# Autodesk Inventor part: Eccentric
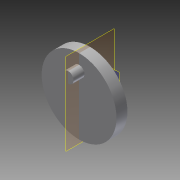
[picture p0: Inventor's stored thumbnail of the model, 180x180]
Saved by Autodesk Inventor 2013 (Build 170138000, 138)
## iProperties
Created: 2008-06
Part Number: Eccentric
Document SubType Name: Modeling
Designer: tangg
Density: 7.85 g/cm^3
Mass: 10.8718 g
Surface Area: 44.2672 cm^2
Volume: 10.8718 cm^3
Stock Number: Eccentric
Material: Steel
Author: tangg
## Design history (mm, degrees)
sketch "Sketch1"
  geometry: C1 r 21.726 at (0, 0); 1 further point
  constraints: 1 centre point, 1 coincident
extrude "Extrusion1" new body sketch "Sketch1" distance "d0" = 6.35; taper "d1" = 0 deg
sketch "Sketch2"
  geometry: C1 r 3.175 at (0, 12.7); 1 further point
  constraints: 1 centre point
  dimensions: "d4" = 6.35 diameter of C1
extrude "Extrusion2" join sketch "Sketch2" distance "d2" = 6.35; taper "d3" = 0 deg
sketch "Sketch5"
  geometry: C1 r 3.175 at (0, 0); C2 r 8.542 at (0, 0); 1 further point
  constraints: 2 centre point, 1 coincident
workplane "Work Plane3"
extrude "Extrusion5" join sketch "Sketch5" distance "d9" = 6.35; taper "d10" = 0 deg
sketch "Sketch6"
  geometry: C1 r 3.175 at (0, 0); 3 further points
  constraints: 2 horizontal alignment, 1 centre point, 4 other
extrude "Extrusion4" join sketch "Sketch6" distance "d7" = 6.35; taper "d8" = 0 deg
sketch "Sketch7"
  geometry: C1 r 3.175 at (0, 0) reference; 3 further points
  constraints: 2 horizontal alignment
  node "Projected Loop1"
body "Solid1"
